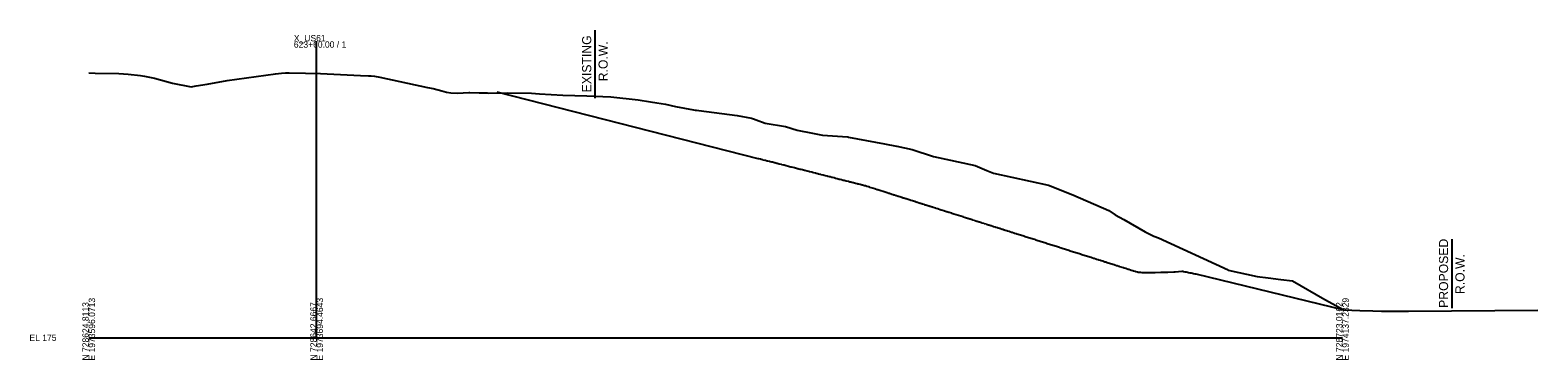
# Model space of a CAD drawing. Extents: x -26 to 1629, y -25 to 9635.
# Drawn here: x -26 to 636, y 8990 to 9135 of the extents above; entities that cross this region are included whole.
import ezdxf

# ---------------------------------------------------------------- set-up
doc = ezdxf.new("R2010")
doc.units = 0
for name, color, linetype in [('Draft_XS_Grid', 7, 'Continuous'), ('DTM_X_GROUND', 7, 'Continuous'), ('XS_CELL', 7, 'Continuous'), ('XS_P_GROUND', 7, 'Continuous'), ('XS_P_ROW', 7, 'Continuous'), ('XS_X_ROW', 7, 'Continuous')]:
    doc.layers.add(name, color=color, linetype=linetype)

msp = doc.modelspace()

# ---------------------------------------------------------------- linework, layer by layer
at = {"layer": 'DTM_X_GROUND'}
msp.add_lwpolyline([(0, 9116.13), (2.77, 9116.07), (13.15, 9115.84), (15.23, 9115.69), (17.35, 9115.53), (22.78, 9114.95), (24.52, 9114.77), (28.93, 9113.85), (36.78, 9111.71), (44.88, 9110.09), (47.09, 9110.45), (51.95, 9111.23), (60.78, 9112.79), (81.9, 9115.81), (84.61, 9116.07), (86.32, 9116.14), (87.87, 9116.22), (95.11, 9116.01), (101.75, 9115.82), (119.2, 9115.04), (122.79, 9114.89), (123.94, 9114.82), (125.44, 9114.73), (127.68, 9114.3), (148.57, 9109.81), (151.09, 9109.25), (154.98, 9108.24), (156.95, 9107.72), (158.9, 9107.48), (161.72, 9107.29), (166.75, 9107.52), (167.25, 9107.56), (171.36, 9107.42), (174.78, 9107.35), (175.38, 9107.3), (183.67, 9107.45), (194.25, 9107.24), (197.69, 9107.01), (207.96, 9106.41), (218.57, 9106.12), (229.01, 9105.72), (241.01, 9104.37), (246.5, 9103.43), (249.25, 9102.98), (253.1, 9102.37), (257.48, 9101.4), (265.37, 9099.94), (266.05, 9099.83), (266.46, 9099.76), (266.62, 9099.74), (267.66, 9099.59), (284.46, 9097.5), (290.75, 9096.28), (291.62, 9095.97), (292.85, 9095.52), (296.77, 9094.11), (305.69, 9092.66), (310.76, 9091.01), (317.56, 9089.67), (321.85, 9088.82), (332.82, 9088.09), (333.05, 9088.04), (333.33, 9088), (349.14, 9085.01), (354.45, 9083.99), (354.58, 9083.98), (361.3, 9082.49), (370.63, 9079.45), (388.83, 9075.51), (393.98, 9073.35), (396.93, 9072.16), (421.06, 9066.94), (431.73, 9062.74), (447.54, 9055.76), (450.3, 9053.93), (454.15, 9051.87), (463.49, 9046.46), (467.27, 9044.51), (469.32, 9043.75), (499.86, 9029.73), (499.89, 9029.72), (499.96, 9029.7), (512.62, 9026.91), (517.37, 9026.34), (522.98, 9025.61), (528.12, 9025.01), (542.29, 9016.82), (550.58, 9012.18), (557.67, 9011.92), (563.34, 9011.75), (567.14, 9011.72), (573.21, 9011.72), (578.96, 9011.7), (635.75, 9012.04)], dxfattribs=at)
at = {"layer": 'XS_CELL'}
for p, q in [((100, 9000), (100, 9130)), ((0, 9000), (100, 9000)), ((100, 9000), (550, 9000))]:
    msp.add_line(p, q, dxfattribs=at)
at = {"layer": 'XS_P_GROUND'}
for points in [[(342.68, 9066.06), (342.49, 9066.11), (342.42, 9066.13), (342.11, 9066.21), (341.41, 9066.39), (340.75, 9066.56), (340.4, 9066.65), (339.49, 9066.88), (339.39, 9066.9), (339.34, 9066.91), (338.38, 9067.16), (337.89, 9067.29), (337.37, 9067.42), (337.08, 9067.49), (336.36, 9067.67), (335.57, 9067.87), (335.35, 9067.93), (334.81, 9068.07), (334.34, 9068.19), (333.98, 9068.28), (333.33, 9068.45), (332.34, 9068.7), (332.32, 9068.7), (331.49, 9068.91), (331.31, 9068.96), (331.04, 9069.03), (330.3, 9069.22), (329.74, 9069.36), (329.29, 9069.47), (328.83, 9069.59), (328.28, 9069.73), (327.6, 9069.9), (327.27, 9069.99), (326.97, 9070.06), (326.26, 9070.24), (326.01, 9070.31), (325.25, 9070.5), (325.03, 9070.56), (324.24, 9070.76), (323.95, 9070.83), (323.23, 9071.01), (322.61, 9071.17), (322.22, 9071.27), (321.29, 9071.51), (321.21, 9071.53), (320.91, 9071.61), (320.2, 9071.79), (319.82, 9071.88), (319.19, 9072.04), (318.9, 9072.12), (318.18, 9072.3), (317.46, 9072.48), (317.17, 9072.56), (316.41, 9072.75), (316.16, 9072.81), (315.96, 9072.86), (315.15, 9073.07), (314.22, 9073.31), (314.14, 9073.33), (314.01, 9073.36), (313.13, 9073.58), (312.52, 9073.74), (312.12, 9073.84), (311.49, 9074), (311.11, 9074.1), (310.96, 9074.13), (310.09, 9074.36), (309.6, 9074.48), (309.08, 9074.61), (308.26, 9074.82), (308.07, 9074.87), (307.49, 9075.02), (307.06, 9075.13), (307.05, 9075.13), (306.05, 9075.38), (306, 9075.4), (305.04, 9075.64), (304.96, 9075.66), (304.03, 9075.9), (303.91, 9075.93), (303.02, 9076.15), (302.87, 9076.19), (302.01, 9076.41), (301.83, 9076.46), (301, 9076.67), (300.79, 9076.72), (299.99, 9076.93), (299.75, 9076.99), (298.98, 9077.18), (298.71, 9077.25), (297.97, 9077.44), (297.69, 9077.51), (296.96, 9077.7), (296.7, 9077.76), (295.95, 9077.95), (295.71, 9078.02), (294.94, 9078.21), (294.72, 9078.27), (293.93, 9078.47), (293.75, 9078.51), (179.2, 9107.66)], [(342.49, 9066.11), (344.88, 9065.38), (345.2, 9065.28), (345.93, 9065.05), (346.21, 9064.96), (349.85, 9063.8)], [(349.85, 9063.8), (350.25, 9063.68), (350.95, 9063.45), (351.12, 9063.4), (351.15, 9063.39), (351.26, 9063.36), (351.28, 9063.35), (352.27, 9063.04), (352.94, 9062.82), (353.28, 9062.71), (353.45, 9062.66), (354.24, 9062.41), (354.29, 9062.39), (354.29, 9062.39), (354.31, 9062.39), (355.06, 9062.15), (355.3, 9062.07), (355.78, 9061.92), (356.31, 9061.75), (356.44, 9061.71), (356.71, 9061.62), (357.06, 9061.51), (357.32, 9061.43), (357.64, 9061.33), (358.03, 9061.21), (358.17, 9061.16), (358.33, 9061.11), (358.68, 9061), (359, 9060.9), (359.15, 9060.85), (359.34, 9060.79), (359.59, 9060.71), (359.78, 9060.65), (360, 9060.58), (360.35, 9060.47), (360.62, 9060.38), (361.36, 9060.15), (362.22, 9059.88), (362.37, 9059.83), (362.73, 9059.72), (362.99, 9059.63), (363.14, 9059.59), (363.32, 9059.53), (363.33, 9059.52), (363.38, 9059.51), (363.72, 9059.4), (363.93, 9059.33), (364.09, 9059.28), (364.25, 9059.23), (364.28, 9059.22), (364.39, 9059.19), (364.81, 9059.06), (364.9, 9059.03), (364.98, 9059), (365.4, 9058.87), (365.48, 9058.84), (365.52, 9058.83), (365.8, 9058.74), (366.41, 9058.55), (366.42, 9058.54), (366.42, 9058.54), (366.57, 9058.5), (366.7, 9058.46), (367, 9058.36), (367.23, 9058.29), (367.28, 9058.27), (367.42, 9058.23), (367.56, 9058.18), (367.58, 9058.18), (367.69, 9058.14), (367.79, 9058.11), (367.95, 9058.06), (368.03, 9058.03), (368.08, 9058.02), (368.3, 9057.95), (368.33, 9057.94), (368.43, 9057.91), (368.46, 9057.9), (368.46, 9057.9), (368.7, 9057.82), (368.78, 9057.79), (368.94, 9057.75), (369.2, 9057.66), (369.28, 9057.64), (369.39, 9057.6), (369.39, 9057.6), (369.44, 9057.59), (369.61, 9057.53), (369.7, 9057.51), (369.93, 9057.43), (370.06, 9057.39), (370.14, 9057.36), (370.45, 9057.27), (370.51, 9057.25), (371.46, 9056.95), (371.71, 9056.87), (372.47, 9056.63), (372.88, 9056.49), (373.48, 9056.3), (374.04, 9056.13), (374.49, 9055.98), (375.17, 9055.77), (375.5, 9055.66), (376.3, 9055.41), (376.51, 9055.34), (377.41, 9055.06), (377.52, 9055.02), (378.51, 9054.71), (378.53, 9054.7), (378.71, 9054.64), (379.54, 9054.38), (379.56, 9054.38), (380.55, 9054.06), (380.59, 9054.05), (381.56, 9053.74), (381.62, 9053.72), (382.57, 9053.42), (382.65, 9053.4), (383.58, 9053.1), (383.68, 9053.07), (384.59, 9052.78), (384.7, 9052.74), (385.6, 9052.46), (385.73, 9052.42), (386.61, 9052.14), (386.76, 9052.09), (387.62, 9051.82), (387.79, 9051.77), (388.63, 9051.5), (388.81, 9051.44), (389.64, 9051.18), (389.84, 9051.11), (390.65, 9050.86), (390.86, 9050.79), (391.66, 9050.54), (391.89, 9050.46), (392.67, 9050.22), (392.91, 9050.14), (393.68, 9049.89), (393.93, 9049.81), (394.69, 9049.57), (394.96, 9049.49), (395.7, 9049.25), (395.98, 9049.16), (396.71, 9048.93), (397, 9048.84), (397.72, 9048.61), (398.03, 9048.52), (398.73, 9048.29), (399.01, 9048.2), (399.62, 9048.01), (399.66, 9048), (399.74, 9047.97), (400.07, 9047.87), (400.75, 9047.65), (401.06, 9047.55), (401.66, 9047.36), (401.69, 9047.35), (401.76, 9047.33), (402.11, 9047.22), (402.77, 9047.01), (403.13, 9046.9), (403.78, 9046.69), (404.15, 9046.57), (404.79, 9046.37), (405.17, 9046.25), (405.8, 9046.05), (406.2, 9045.92), (406.81, 9045.73), (407.21, 9045.6), (407.82, 9045.41), (408.23, 9045.28), (408.83, 9045.09), (409.25, 9044.95), (409.84, 9044.77), (410.27, 9044.63), (410.85, 9044.45), (411.29, 9044.31), (411.86, 9044.13), (412.31, 9043.98), (412.87, 9043.81), (413.33, 9043.66), (413.88, 9043.48), (414.35, 9043.34), (414.89, 9043.16), (415.37, 9043.01), (415.9, 9042.84), (416.38, 9042.69), (416.91, 9042.52), (417.4, 9042.37), (417.92, 9042.2), (418.42, 9042.04), (418.93, 9041.88), (419.44, 9041.72), (419.94, 9041.56), (420.46, 9041.4), (420.95, 9041.24), (421.47, 9041.08), (421.96, 9040.92), (422.49, 9040.75), (422.97, 9040.6), (423.51, 9040.43), (423.98, 9040.28), (424.52, 9040.11), (424.99, 9039.96), (425.47, 9039.81), (425.87, 9039.68), (425.94, 9039.66), (426, 9039.64), (426.56, 9039.46), (427.01, 9039.32), (427.57, 9039.14), (428.02, 9039), (428.59, 9038.82), (429.03, 9038.68), (429.61, 9038.5), (430.04, 9038.36), (430.62, 9038.17), (431.05, 9038.04), (431.64, 9037.85), (432.06, 9037.72), (432.65, 9037.53), (433.07, 9037.4), (433.67, 9037.21), (434.08, 9037.08), (434.69, 9036.88), (435.09, 9036.75), (435.7, 9036.56), (436.1, 9036.43), (436.72, 9036.24), (437.11, 9036.11), (437.73, 9035.92), (438.12, 9035.79), (438.75, 9035.6), (439.13, 9035.47), (439.76, 9035.27), (440.14, 9035.15), (440.78, 9034.95), (441.15, 9034.83), (441.79, 9034.63), (442.16, 9034.51), (442.81, 9034.31), (443.17, 9034.19), (443.82, 9033.98), (444.18, 9033.87), (444.84, 9033.66), (445.19, 9033.55), (445.85, 9033.34), (446.2, 9033.23), (446.87, 9033.02), (447.21, 9032.91), (447.88, 9032.7), (448.22, 9032.59), (448.9, 9032.37), (449.23, 9032.27), (449.91, 9032.05), (450.24, 9031.95), (450.93, 9031.73), (451.25, 9031.63), (451.85, 9031.44), (452.13, 9031.35), (452.22, 9031.32), (452.26, 9031.31), (452.78, 9031.14), (453.02, 9031.07), (453.2, 9031.01), (453.27, 9030.99), (453.97, 9030.77), (454.29, 9030.67), (454.98, 9030.44), (455.3, 9030.34), (456, 9030.12), (456.31, 9030.02), (457.01, 9029.8), (457.32, 9029.7), (458.02, 9029.48), (458.33, 9029.38), (459.04, 9029.16), (459.34, 9029.06), (460.05, 9028.84), (460.35, 9028.74), (460.59, 9028.72), (461.44, 9028.69), (461.94, 9028.68), (464.4, 9028.65), (464.92, 9028.66), (467.34, 9028.66), (467.88, 9028.67), (470.32, 9028.72), (472.87, 9028.8), (473.38, 9028.81), (476.08, 9028.94), (476.57, 9028.96), (479.5, 9029.14), (479.95, 9029.16), (480.36, 9029.08), (480.93, 9028.96), (481.39, 9028.87), (482.02, 9028.74), (482.5, 9028.64), (483.12, 9028.51), (483.6, 9028.42), (484.21, 9028.29), (484.7, 9028.19), (485.3, 9028.07), (485.7, 9027.98), (550.58, 9012.18)]]:
    msp.add_lwpolyline(points, dxfattribs=at)
at = {"layer": 'XS_P_ROW'}
msp.add_line((598, 9043.23), (598, 9012.91), dxfattribs=at)
at = {"layer": 'XS_X_ROW'}
msp.add_line((222, 9134.9), (222, 9105), dxfattribs=at)

# ---------------------------------------------------------------- texts
at = {"layer": 'Draft_XS_Grid'}
msp.add_text('-', height=0.0001, dxfattribs=at).set_placement((0, 9000))
at = {"layer": 'XS_CELL'}
for s, p in [('X_US61', (90, 9130)), ('623+60.00 / 1', (90, 9127.2)), ('EL 175', (-26, 8998.6))]:
    msp.add_text(s, height=2.8, dxfattribs=at).set_placement(p)
for s, p in [('N 728624.8113', (0, 8990)), ('E 1973596.0713', (2.8, 8990)), ('E 1973694.4643', (102.8, 8990)), ('E 1974137.2329', (552.8, 8990)), ('N 728642.6667', (100, 8990)), ('N 728723.0162', (550, 8990))]:
    msp.add_text(s, height=2.8, rotation=90, dxfattribs=at).set_placement(p)
at = {"layer": 'XS_P_ROW'}
for s, p in [('PROPOSED', (596.37, 9013.09)), ('R.O.W.', (603.57, 9019.16))]:
    msp.add_text(s, height=4, rotation=90, dxfattribs=at).set_placement(p)
at = {"layer": 'XS_X_ROW'}
for s, p in [('EXISTING', (220.47, 9107.64)), ('R.O.W.', (227.67, 9112.48))]:
    msp.add_text(s, height=4, rotation=90, dxfattribs=at).set_placement(p)

doc.saveas('drawing.dxf')
